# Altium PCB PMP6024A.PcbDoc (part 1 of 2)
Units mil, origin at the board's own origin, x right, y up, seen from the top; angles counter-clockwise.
Board outline 5700 x 1771.65 mil, 2 copper layers (Top Layer, Bottom Layer), stack 62 mil thick; 185 components, 92 nets, 398 pads, 91 vias.
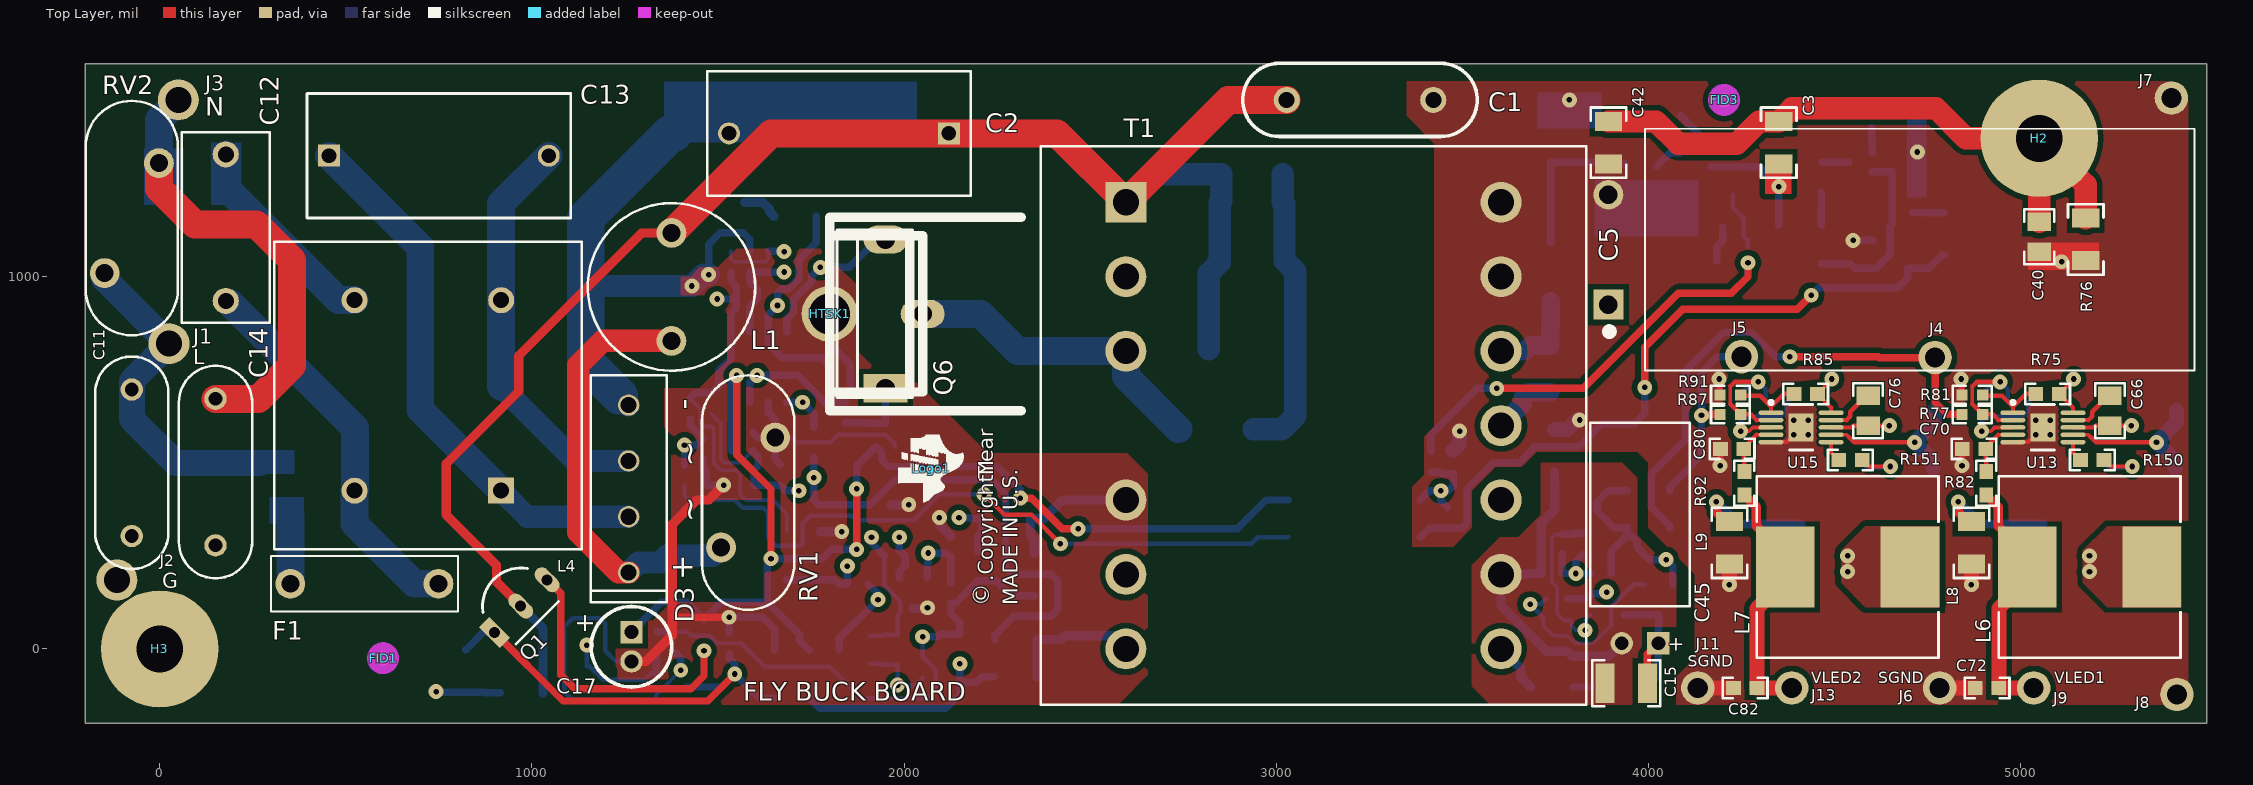
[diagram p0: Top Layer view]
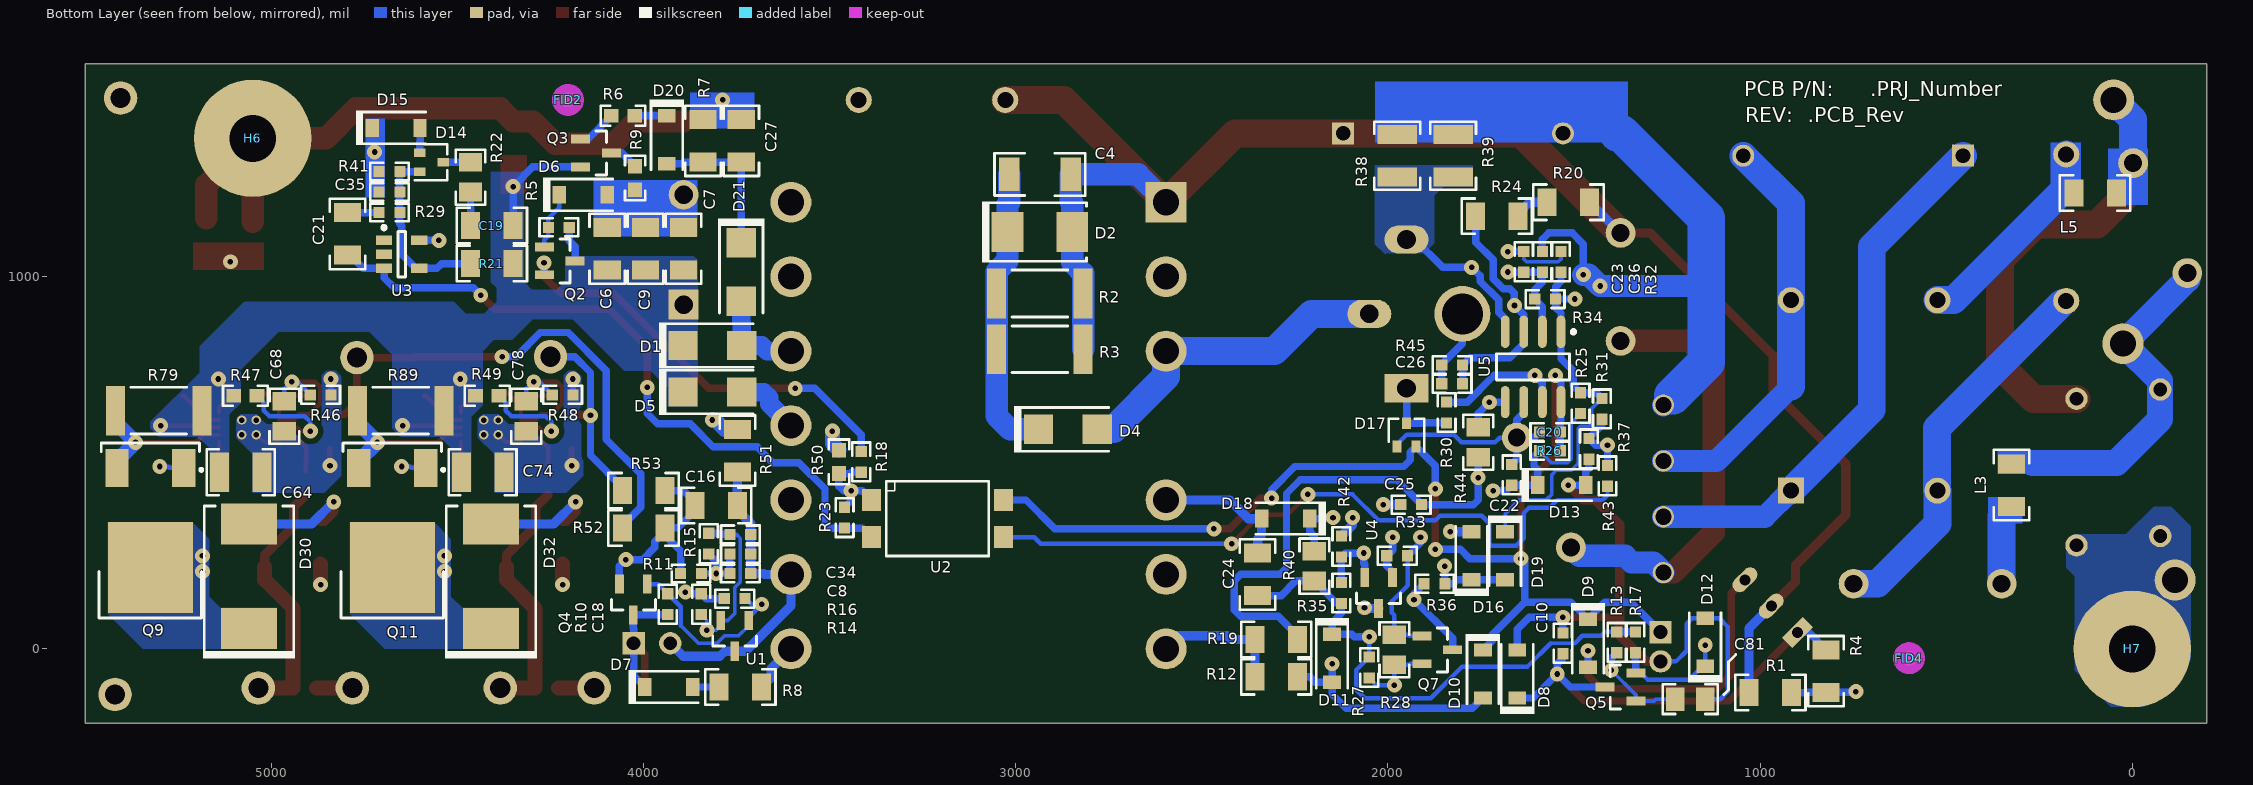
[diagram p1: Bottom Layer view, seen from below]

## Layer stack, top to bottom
Top Layer: signal copper 1.4
Dielectric: core 59.2, FR-4, Dk 4.8
Bottom Layer: signal copper 1.4

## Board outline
-200,-200 -200,1571.65 5500,1571.65 5500,-200

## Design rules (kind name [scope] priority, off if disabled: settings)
AcuteAngle [All] p1: minimum=4.50000000000000E+0001 checktracksonly=FALSE
AssemblyTestPointUsage [All] p1: valid=2
Clearance Clearance_U13&U15 [InComponent('U13')or InComponent('U15')] p1: gap=7
Clearance Poly_clearance [InPoly] p2: gap=15
Clearance [All] p3: gap=8
ComponentClearance TO-220+heatsink [InComponent('HTSK1') vs InComponent('Q6')] p1: gap=-1 collisioncheckmode=3 verticalgap=-1 showdistances=FALSE
ComponentClearance Hardware [(HasFootprint('NY PMS 440 0025 PH')) vs HasFootprint('Keystone_1902C')] p2: gap=-1 collisioncheckmode=3 verticalgap=-1 showdistances=FALSE
ComponentClearance ComponentClearance_SmallPassives [HasFootprint('0201*') or HasFootprint('0402*') or HasFootprint('0508') or HasFootprint('0603*') or HasFootprint('0612') or HasFootprint('0805*') or HasFootprint('0815*') or HasFootprint('0830*') or HasFootprint('1206*') or HasFootprint('1210*') or HasFootprint('1808*') or HasFootprint('1812*') or HasFootprint('1825*') or HasFootprint('2010*') or HasFootprint('2220*') or HasFootprint('2225*') or HasFootprint('2512*') or HasFootprint('2728*') or HasFootprint('3518*') vs HasFootprint('0201*') or HasFootprint('0402*') or HasFootprint('0508') or HasFootprint('0603*') or HasFootprint('0612') or HasFootprint('0805*') or HasFootprint('0815*') or HasFootprint('0830*') or HasFootprint('1206*') or HasFootprint('1210*') or HasFootprint('1808*') or HasFootprint('1812*') or HasFootprint('1825*') or HasFootprint('2010*') or HasFootprint('2220*') or HasFootprint('2225*') or HasFootprint('2512*') or HasFootprint('2728*') or HasFootprint('3518*')] p3: gap=10 collisioncheckmode=3 verticalgap=10 showdistances=FALSE
ComponentClearance [All] p4: gap=1 collisioncheckmode=3 verticalgap=1 showdistances=FALSE
DiffPairsRouting [All] p1: maxlimit=100 minlimit=10 mostfreqgap=10 maxuncoupledlength=1000
FabricationTestPointUsage TestPointUsage [All] p1: valid=2 allowmultiple=FALSE
FabricationTestpoint Testpoint [All] p1: side=3 testpointundercomponent=TRUE minsize=40 maxsize=100 preferedsize=60 minholesize=0 maxholesize=40 preferedholesize=32 testpointgrid=1 allowsidetop=TRUE allowsidebottom=TRUE usegrid=TRUE gridtolerance=0.01
FanoutControl Fanout_LCC [IsLCC] p1: bgadir=Out bgaviamode=Centered fanoutstyle=Auto fanoutdirection=Alternating viagrid=1 // Fanout_LCC (Default Rule)
FanoutControl Fanout_BGA [IsBGA] p2: bgadir=Out bgaviamode=Centered fanoutstyle=Auto fanoutdirection=Alternating viagrid=1 // Fanout_BGA (Default Rule)
FanoutControl Fanout_Default [All] p4: bgadir=Out bgaviamode=Centered fanoutstyle=Auto fanoutdirection=Alternating viagrid=1 // Fanout_Default (Default Rule)
FanoutControl Fanout_Small [(CompPinCount < 5)] p5: bgadir=Out bgaviamode=Centered fanoutstyle=Auto fanoutdirection=OutThenIn viagrid=1 // Fanout_Small (Default Rule)
Height [All] p1: minheight=0 maxheight=1500 prefheight=500
HoleSize [All] p1: absolutevalues=TRUE maxlimit=251 minlimit=8 maxpercent=80.000 minpercent=20.000
MinimumAnnularRing [All] p1: minimumring=4.9
MinimumSolderMaskSliver MinimumSolderMaskSliver_Logo [InComponentClass('Logo') vs InComponentClass('Logo')] p1: minsoldermaskwidth=0.7
MinimumSolderMaskSliver [All] p2: minsoldermaskwidth=4
PlaneConnect [All] p1: planeconnectstyle=Relief reliefexpansion=10 reliefentries=4 reliefconductorwidth=10 reliefairgap=10
PolygonConnect [All] p1: connectstyle=Direct reliefconductorwidth=10 reliefentries=4 polygonreliefangle="90 Angle" airgapwidth=10
RoutingVias [All] p1: holewidth=15 width=32 viastyle="Through Hole" minholewidth=15 minwidth=25 maxholewidth=15 maxwidth=40
SMDToCorner [All] p1 off: distance=30000
SilkToSilkClearance [All] p1: silktosilkclearance=5
SilkscreenOverComponentPads [All] p1: minsilkscreentomaskgap=5
SolderMaskExpansion [All] p1: expansion=3
UnRoutedNet [All] p1 off:
Width [All] p1: maxlimit=100 minlimit=6 preferedwidth=10 checkconnectedcopper=TRUE
12 further rules are at their usual default settings.

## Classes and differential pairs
component class AssemblyNote: ZZ2 ZZ3 ZZ4
component class FiducialMark: FID1 FID2 FID3 FID4
component class PMP6024A_Hardware: FID1 FID2 FID3 FID4 Logo1 ZZ2 ZZ3 ZZ4
component class Logo: Logo1
component class "Mounting Holes": H2 H3
component class PMP6024A_pg1: C1 C2 C3 C4 C5 C6 C7 C8 C9 C10 C11 C12 C13 C14 C15 C16 C17 C18 C19 C20 C21 C22 C23 C24 C25 C26 C27 C34 C35 C36 C42 C45 C81 D1 D2 D3 D4 D5 D6 D7 D8 D9 D10 D11 D12 D13 D14 D15 D16 D17 D18 D19 D20 D21 F1 H2 H3 H6 H7 HTSK1 J1 J2 J3 L1 L3 L4 L5 Q1 Q2 Q3 Q4 Q5 Q6 Q7 R1 R2 R3 R4 R5 R6 R7 R8 R9 R10 R11 R12 R13 R14 R15 R16 R17 R18 R19 R20 R21 R22 R23 R24 R25 R26 R27 R28 R29 R30 R31 R32 R33 R34 R35 R36 R37 R38 R39 R40 R41 R42 R43 R44 R45 R50 R51 R76 RV1 RV2 T1 U1 U2 U3 U4 U5
component class PMP6024A_pg2: C40 C64 C66 C68 C70 C72 C74 C76 C78 C80 C82 D30 D32 J4 J5 J6 J7 J8 J9 J11 J13 L6 L7 L8 L9 Q9 Q11 R46 R47 R48 R49 R52 R53 R75 R77 R79 R81 R82 R85 R87 R89 R91 R92 R150 R151 U13 U15

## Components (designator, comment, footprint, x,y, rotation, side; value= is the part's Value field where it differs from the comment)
C1 "VY1472M63Y5UQ63V0" Cap_NP_16Dx5W-10LS 3225,1475 r180 top
C2 "B32922C3334M" B32922_14.5mm 1825,1385 r180 top locked
C3 "GRM319R72A104KA01D" 1206 4350,1360 r90 top
C4 "VJ1808Y103KXGAT" 1808 2935,1275 r0 bottom
C5 "UPW1J102MHD6" CAP_POL-16.5Dx37.5T-7.5LS_Horz 3892.5,925 r90 top locked
C6 "GRM31CR72A105KA01L" 1206 4097.5,1075 r90 bottom
C7 "GRM31CR72A105KA01L" 1206 3892.5,1075 r90 bottom
C8 "C0603C222K5RACTU" 0603_HV 3740,255 r180 bottom
C9 "GRM31CR72A105KA01L" 1206 3995,1075 r90 bottom
C10 "DNP" 0603_HV 1530,15 r90 bottom
C11 "VY2682M59Y5US63V0" Cap_NP_14.5Lx5W-10LS -75,500 r270 top
C12 "B32921C3104M" Cap_NP_13Lx6W-10LS 177.5,935 r90 top
C13 "B32922C3334M" B32922_14.5mm 750,1325 r0 top locked
C14 "VY2682M59Y5US63V0" Cap_NP_14.5Lx5W-10LS 150,475 r90 top locked
C15 "GRM32RR71H105KA01L" 1210 3940,-92.5 r180 top
C16 "GRM31CR72A105KA01L" 1206 3805,385 r180 bottom
C17 "EEU-EB1E470S" Cap_Pol_5Dx11T-2LS 1267.5,45 r270 top
C18 "GRM1885C2A471JA01D" 0603_HV 3845,120 r270 bottom
C19 "GRM31MR72A474KA35L" 1206 4407.5,1137.5 r0 bottom
C20 "GRM188R71H104KA93D" 0603_HV 1565,582.5 r0 bottom
C21 "GRM31CR71A106KA01L" 1206 4795,1115 r90 bottom
C22 "GRM188R71E224KA88D" 0603_HV 1667.5,467.5 r90 bottom
C23 "GRM188R71H104KA93D" 0603_HV 1635,1040 r270 bottom
C24 "GRM31CR72A105KA01L" 1206 2350,200 r90 bottom
C25 "GRM1885C2A220JA01D" 0603_HV 1937.5,387.5 r180 bottom
C26 "GRM188R72A102KA01D" 0603_HV 1827.5,712.5 r0 bottom
C27 "GRM31CR72A105KA01L" 1206 3737.5,1365 r90 bottom
C34 "GRM1885C2A471JA01D" 0603_HV 3740,307.5 r180 bottom
C35 "C0603C222K5RACTU" 0603_HV 4682.5,1227.5 r0 bottom
C36 "C0603C222K5RACTU" 0603_HV 1585,1040 r90 bottom
C40 "C0805C104K1RACTU" 0805_HV 5050,1107.5 r90 top
C42 "GRM319R72A104KA01D" 1206 3892.5,1360 r270 top
C45 "UPW1H470MED" Cap_Pol_6.3Dx11T-2.5LS_horz 3977.5,15 r180 top locked
C64 "HMK325B7225KN-T" 1210 5082.5,475 r0 bottom
C66 "GRM21BR71H105KA12L" 0805_HV 5240,640 r270 top
C68 "GRM21BR61C106KE15L" 0805_HV 4965,625 r270 bottom
C70 "GRM188R71H471KA01D" 0603 4875,537.5 r180 top
C72 "GRM188R71H103KA01D" 0603 4910,-105 r180 top
C74 "HMK325B7225KN-T" 1210 4432.5,475 r0 bottom
C76 "GRM21BR71H105KA12L" 0805_HV 4590,640 r270 top
C78 "GRM21BR61C106KE15L" 0805_HV 4315,625 r270 bottom
C80 "GRM188R71H471KA01D" 0603 4225,537.5 r180 top
C81 "C2012X5R1C475K125AC" 0805_HV 1187.5,-135 r180 bottom
C82 "GRM188R71H103KA01D" 0603 4260,-105 r180 top
D1 "MURA140T3G" SMA 3815,815 r180 bottom
D2 "P6SMB220A" SMB 2935,1120 r180 bottom
D3 "2KBP08M-E4/51" KBPM 1260,430 r90 top locked
D4 "US1K-E3/61T" SMA 2860,590 r180 bottom
D5 "MURA140T3G" SMA 3815,690 r180 bottom
D6 "MMSZ5240B-7-F" SOD-123 4162.5,1220 r180 bottom
D7 "BAV19W-7-F" SOD-123 3932.5,-102.5 r180 bottom
D8 "MMSZ5248B-7-F" SOD-123 1652.5,-67.5 r90 bottom
D9 "BAV19W-7-F" SOD-123 1462.5,15 r270 bottom
D10 "BAV19W-7-F" SOD-123 1745,-67.5 r270 bottom
D11 "BAV19W-7-F" SOD-123 2150,-25 r270 bottom
D12 "MMSZ5240B-7-F" SOD-123 1147.5,17.5 r90 bottom
D13 "MMSZ5240B-7-F" SOD-123 1532.5,440 r180 bottom
D14 "BAV99WT1G" SOT-323 4570,1307.5 r180 bottom
D15 "MMSZ5230B-7-F" SOD-123 4665,1400 r180 bottom
D16 "MMSZ5225B-7-F" SOD-123 1775,250 r90 bottom
D17 "BAV99WT1G" SOT-323 1950,575 r90 bottom
D18 "MMSZ5245B-7-F" SOD-123 2275,350 r0 bottom
D19 "BAV19W-7-F" SOD-123 1685,250 r270 bottom
D20 "MMSZ5230B-7-F" SOD-123 3937.5,1367.5 r270 bottom
D21 "MURA140T3G" SMA 3737.5,1012.5 r270 bottom
D30 "CDBC560-G" SMC 5060,195 r90 bottom
D32 "CDBC560-G" SMC 4410,195 r90 bottom
F1 "0447003.YXP" Fuse_447series 550,175 r180 top
FID1 "Fiducial" Fiducial10-20 600,-25 r0 top
FID2 "Fiducial" Fiducial10-20 4203,1475 r180 bottom
FID3 "Fiducial" Fiducial10-20 4203,1475 r0 top
FID4 "Fiducial" Fiducial10-20 600,-25 r180 bottom
H2 "NY PMS 440 0025 PH" "NY PMS 440 0025 PH" 5050,1371.65 r0 top
H3 "NY PMS 440 0025 PH" "NY PMS 440 0025 PH" 0,0 r0 top
H6 "1902C" Keystone_1902C 5050,1371.65 r180 bottom locked
H7 "1902C" Keystone_1902C 0,0 r180 bottom locked
HTSK1 "7141DG" Htsk_7147DG 1800,900 r270 top locked
J1 "TESTPOINT" Hole_R110D70 25,820 r0 top
J2 "TESTPOINT" Hole_R110D70 -115,185 r0 top
J3 "TESTPOINT" Hole_R110D70 50,1475 r0 top
J4 "NA" "CONN-18GA WIRE" 4770,782.5 r0 top
J5 "NA" "CONN-18GA WIRE" 4250,785 r90 top
J6 "NA" "CONN-18GA WIRE" 4782.5,-105 r180 top
J7 "NA" "CONN-18GA WIRE" 5405,1480 r0 top
J8 "NA" "CONN-18GA WIRE" 5420,-122.5 r0 top
J9 "NA" "CONN-18GA WIRE" 5035,-105 r180 top
J11 "NA" "CONN-18GA WIRE" 4132.5,-105 r90 top
J13 "NA" "CONN-18GA WIRE" 4385,-105 r90 top
L1 "RFB1010-561L" Indt_RL5480-4 1375,827.5 r90 top locked
L3 "HI1206T161R-10" 1206 325,440 r270 bottom
L4 "EH20-0.8-02-5M6" Schaffner_EH20-0.8-02-5M6 917.5,425 r90 top locked
L5 "HI1206T161R-10" 1206 100,1225 r0 bottom
L6 "MSS1260-154KL" MSS1260 5185.3,220 r180 top
L7 "MSS1260-154KL" MSS1260 4535.3,220 r180 top
L8 "HI1206T161R-10" 1206 4867.5,285 r90 top
L9 "HI1206T161R-10" 1206 4217.5,285 r90 top
Logo1 "Texas Instruments" TI_Symbol_Overlay_Small 2072.5,485 r90 top
Q1 "FQN1N60CTA" TO92_modified 970,115 r315 top
Q2 "MMBT3904" MF03A_N 4225,1042.5 r180 bottom
Q3 "MMBTA56-7-F" MF03A_N 4127.5,1332.5 r180 bottom
Q4 "MMBT3904" MF03A_N 4027.5,132.5 r270 bottom
Q5 "MMBT3904" MF03A_N 1375,-102.5 r0 bottom
Q6 "STP10NK80ZFP" TO-220AB-wide 1950,900 r90 top locked
Q7 "MMBT3906-7-F" MF03A_N 1867.5,-2.5 r180 bottom
Q9 "ZXMP7A17KTC" DPAK 5325,352.5 r270 bottom
Q11 "ZXMP7A17KTC" DPAK 4675,352.5 r270 bottom
R1 "CRCW1206499KFKEA" 1206 972.5,-117.5 r180 bottom
R2 "CRCW251262K0JNEG" 2512 2935,955 r180 bottom
R3 "DNP" 2512 2935,805 r180 bottom
R4 "CRCW1206499KFKEA" 1206 822.5,-60 r90 bottom
R5 "CRCW060349K9FKEA" 0603_HV 4227.5,1132.5 r180 bottom
R6 "CRCW060320K0FKEA" 0603 4055,1432.5 r0 bottom
R7 "CRCW1206200KFKEA" 1206 3840,1365 r270 bottom
R8 "CRCW120620R0JNEA" 1206 3740,-102.5 r0 bottom
R9 "CRCW06031K00FKEA" 0603 4022.5,1265 r90 bottom
R10 "CRCW06032K21FKEA" 0603_HV 3935,120 r270 bottom
R11 "CRCW0603249KFKEA" 0603_HV 3872.5,202.5 r0 bottom
R12 "CRCW120620R0JNEA" 1206 2300,-75 r180 bottom
R13 "CRCW0603100KFKEA" 0603_HV 1385,17.5 r90 bottom
R14 "CRCW06031M00FKEA" 0603_HV 3755,135 r180 bottom
R15 "CRCW060310K0FKEA" 0603_HV 3825,282.5 r270 bottom
R16 "CRCW060349K9FKEA" 0603_HV 3740,202.5 r0 bottom
R17 "CRCW06031K00JNEA" 0603_HV 1335,17.5 r90 bottom
R18 "CRCW06031K00JNEA" 0603_HV 3415,502.5 r90 bottom
R19 "CRCW120622K1FKEA" 1206 2300,25 r0 bottom
R20 "CRCW12061M00FKEA" 1206 1515,1200 r180 bottom
R21 "CRCW1206499KFKEA" 1206 4407.5,1035 r0 bottom
R22 "CRCW0805150RFKEA" 0805_HV 4465,1267.5 r270 bottom
R23 "CRCW0603100KFKEA" 0603_HV 3460,352.5 r90 bottom
R24 "CRCW12061M00FKEA" 1206 1707.5,1162.5 r180 bottom
R25 "CRCW0603681KFKEA" 0603_HV 1482.5,660 r90 bottom
R26 "CRCW060349K9FKEA" 0603_HV 1565,532.5 r180 bottom
R27 "CRCW060310R0FKEA" 0603_HV 2050,-50 r270 bottom
R28 "CRCW0805150RFKEA" 0805_HV 1982.5,-2.5 r270 bottom
R29 "CRCW060320K0FKEA" 0603_HV 4682.5,1172.5 r0 bottom
R30 "CRCW060320R0FKEA" 0603_HV 1842.5,635 r270 bottom
R31 "CRCW060347K5FKEA" 0603_HV 1425,645 r90 bottom
R32 "CRCW060347K5FKEA" 0603_HV 1535,1040 r270 bottom
R33 "CRCW06032K21FKEA" 0603_HV 1975,250 r180 bottom
R34 "CRCW060375K0FKEA" 0603_HV 1577.5,940 r180 bottom
R35 "CRCW060375K0FKEA" 0603_HV 2125,150 r270 bottom
R36 "CRCW06031K00JNEA" 0603_HV 1875,175 r180 bottom
R37 "CRCW06032K21FKEA" 0603_HV 1460,537.5 r90 bottom
R38 "MCR25JZHFLR470" 1210 1975,1325 r270 bottom
R39 "MCR25JZHFLR470" 1210 1825,1325 r270 bottom
R40 "CRCW0805150RFKEA" 0805_HV 2197.5,222.5 r270 bottom
R41 "CRCW060312K7FKEA" 0603_HV 4682.5,1282.5 r180 bottom
R42 "CRCW060314K3FKEA" 0603_HV 2125,275 r270 bottom
R43 "CRCW06034K99FKEA" 0603_HV 1410,465 r270 bottom
R44 "CRCW0805150RFKEA" 0805_HV 1757.5,555 r90 bottom
R45 "CRCW060312K1FKEA" 0603_HV 1827.5,762.5 r180 bottom
R46 "CRCW06032K87FKEA" 0603_HV 4867.5,682.5 r180 bottom
R47 "CRCW0603100KFKEA" 0603 5070,680 r180 bottom
R48 "CRCW06032K87FKEA" 0603_HV 4217.5,682.5 r180 bottom
R49 "CRCW0603100KFKEA" 0603 4420,680 r180 bottom
R50 "CRCW0603100KFKEA" 0603 3475,502.5 r270 bottom
R51 "CRCW12060000Z0EA" 1206 3747.5,532.5 r90 bottom
R52 "CRCW1206280KFKEA" 1206 4000,325 r0 bottom
R53 "CRCW1206280KFKEA" 1206 4000,425 r0 bottom
R75 "CRCW0603249KFKEA" 0603 5072.5,685 r180 top
R76 "CRCW12061M00FKEA" 1206 5175,1100 r270 top
R77 "CRCW060310K0FKEA" 0603_HV 4870,630 r180 top
R79 "ERJ-1TRSJR18U" 2512 5302.5,640 r180 bottom
R81 "CRCW06036K98FKEA" 0603_HV 4870,682.5 r0 top
R82 "CRCW060364K9FKEA" 0603 4907.5,445 r90 top
R85 "CRCW0603200KFKEA" 0603 4422.5,685 r180 top
R87 "CRCW060310K0FKEA" 0603_HV 4220,630 r180 top
R89 "ERJ-1TRSJR18U" 2512 4652.5,640 r180 bottom
R91 "CRCW06036K98FKEA" 0603_HV 4220,682.5 r0 top
R92 "CRCW060364K9FKEA" 0603 4257.5,445 r90 top
R150 "CRCW06036R80JNEA" 0603 5192.5,507.5 r0 top
R151 "CRCW06036R80JNEA" 0603 4542.5,507.5 r0 top
RV1 "S14K320E2K1" MOV_S14K320E2K1 1581,420 r270 top locked
RV2 "S14K320E2K1" MOV_S14K320E2K1 -75,1157.5 r270 top
T1 "" Xfmr_ETD29H_Wurth 3100,600 r0 top locked
U1 "LM431BIM3" MF03A_N 3755,35 r270 bottom
U2 "FOD817ASD" FOD81XASD 3210,350 r180 bottom
U3 "LMV431AIM5X" MF05A_N 4650,1060 r180 bottom
U4 "LM431BIM3" MF03A_N 2025,150 r270 bottom
U5 "UCC28811DR" D0008A_N 1610,757.5 r270 bottom
U13 "LM3409HVMY/NOPB" MUC10A_N 5060,595 r0 top
U15 "LM3409HVMY/NOPB" MUC10A_N 4410,595 r0 top
ZZ2 "These assemblies are ESD sensitive, ESD precautions shall be observed." AssemblyNote 2.5,2031.61 r0 top
ZZ3 "These assemblies must be clean and free from flux and all contaminants. Use of no clean flux is not acceptable." AssemblyNote 2.5,1943.06 r0 top
ZZ4 "These assemblies must comply with workmanship standards IPC-A-610 Class 2., unless otherwise specified." AssemblyNote 2.5,1854.5 r0 top

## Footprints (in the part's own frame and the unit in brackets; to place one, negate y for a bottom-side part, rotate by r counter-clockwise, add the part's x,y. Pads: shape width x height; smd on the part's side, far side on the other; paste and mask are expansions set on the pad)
0603 [mm] "0603 from SM-752 data"
  rect 1x0.95 smd: 1(-0.8,0) 2(0.8,0)
  silkscreen extent -1.52,-0.69 1.52,0.69, body extent -0.87,-0.47 0.87,0.47, height 0.85
0603_HV [mil] "Ernesto recommended land pattern.  26 mil between pads."
  rect 30x30 smd: 1(-28,0) 2(28,0)
  silkscreen extent -52,-24 52,24, body extent -34,-19 34,19, height 33
0805_HV [mil] "0805 with 30mil clearance between pads"
  rect 50x63 smd: 1(-40,0) 2(40,0)
  silkscreen extent -74,-40 74,40, body extent -43,-29 43,29, height 43
1206 [mm] "1206 from SM-752 data"
  rect 1.3x1.85 smd: 1(-1.45,0) 2(1.45,0)
  silkscreen extent -2.4,-1.21 2.4,1.21, body extent -1.7,-0.9 1.7,0.9, height 1.35
1210 [mm] "1210 from SM-752 data"
  rect 1.3x2.7 smd: 1(-1.45,0) 2(1.45,0)
  silkscreen extent -2.32,-1.57 2.32,1.57, body extent -1.7,-1.35 1.7,1.35, height 1.35
1808 [mm] "Chip Capacitor, Body 4.6x2.0mm, IPC Medium Density"
  rect 1.4x2.3 smd: 1(-2.1,0) 2(2.1,0)
  silkscreen extent -3.1,-1.45 3.1,1.45, body extent -2.47,-1.2 2.47,1.2, height 2.03
2512 [mm] "Chip Resistor, Body 6.3x3.2mm, IPC Medium Density"
  rect 1.3x3.4 smd: 1(-2.95,0) 2(2.95,0)
  silkscreen extent -1.9,-1.6 1.9,1.6, body extent -3.22,-1.67 3.22,1.67, height 0.71
AssemblyNote [mil] "Assembly Note"
B32922_14.5mm [mm] "Epcos film capacitors, 15mm spacing"
  rect 1.5x1.5 hole 1: 1(-7.5,0)
  round 1.5 hole 1: 2(7.5,0)
  silkscreen extent -9,-4.25 9,4.25, body extent -9,-4.25 9,4.25, height 14.5
Cap_NP_13Lx6W-10LS [mil] "Epcos P/N B32921C3104M"
  round 70 hole 43: 1(0,0) 2(393.7,0)
  silkscreen extent -59,-118 453,118, body extent -59,-118 453,118, height 472
Cap_NP_14.5Lx5W-10LS [mil]
  round 60 hole 37: 1(-196.85,0) 2(196.85,0)
  silkscreen extent -285,-98 285,98, body extent -284,-100 284,97, height 688
Cap_NP_16Dx5W-10LS [mil]
  round 70 hole 43: 1(-196.85,0) 2(196.85,0)
  silkscreen extent -315,-98 315,98, body extent -312,-97 315,99, height 787
CAP_POL-16.5Dx37.5T-7.5LS_Horz [mil] "Nichicon P/N UPW1J102MHD6"
  rect 80x80 hole 50: 1(0,0)
  round 80 hole 50: 2(295.28,0)
  silkscreen extent -177,-1575 472,7, body extent -177,-1575 471,-99, height 915
Cap_Pol_5Dx11T-2LS [mil]
  rect 60x60 hole 37: 1(0,0)
  round 60 hole 37: 2(78.74,0)
  silkscreen extent -69,-108 148,108, body extent -68,-108 148,108, height 472
Cap_Pol_6.3Dx11T-2.5LS_horz [mil]
  rect 60x60 hole 37: 1(-49.21,0)
  round 60 hole 37: 2(49.21,0)
  silkscreen extent -134,-592 134,-100, body extent -133,-592 133,-100, height 299
"CONN-18GA WIRE" [mil]
  round 90 hole 54: 1(0,0)
D0008A_N [mm] "SOIC, 8-Leads, Body 4.9x3.9mm, Pitch 1.27mm, IPC Medium Density"
  oval 2.2x0.6 smd: 1(-2.4,1.905) 2(-2.4,0.635) 3(-2.4,-0.635) 4(-2.4,-1.905) 5(2.4,-1.905) 6(2.4,-0.635) 7(2.4,0.635) 8(2.4,1.905)
  silkscreen extent -2.52,-2.5 0.9,2.88, body extent -2,-2.5 2,2.5, height 1.75
DPAK [mm] "D-PAK, 3-Pads, Body 6.22x6.73mm (max), TO-252AA using nominal STEP model"
  rect 2.6x1.6 smd: 1(-3.4,2.28) 3(-3.4,-2.28)
  rect 6.2x5.8 smd paste-2.9: 4(3.4,0)
  silkscreen extent -5.1,-3.5 6.83,3.55, body extent -3.86,-3.29 5.84,3.29, height 2.48
Fiducial10-20 [mm]
  round 1 smd paste-0.5 mask+0.5: 1(0,0)
  Keep-Out Layer circle w1.178: c0,0 r0.5
FOD81XASD [mm] "Fairchild FOD814-817ASD series high temp optocouplers"
  rect 1.3x1.5 smd mask+0.076: 1(-4.5,1.27) 2(-4.5,-1.27) 3(4.5,-1.27) 4(4.5,1.27)
  silkscreen extent -3.5,-2.55 3.5,2.55, body extent -3.5,-2.55 3.5,2.55, height 4
Fuse_447series [mil] "Littelfuse 447 series"
  round 80 hole 48: 1(-199.02,0) 2(199.02,0)
  silkscreen extent -251,-75 251,75, body extent -251,-75 251,75, height 345
Hole_R110D70 [mil]
  round 110 hole 70: 1(0,0)
Htsk_7147DG [mil] "Aavid P/N 7147DG TO-220 heatsink"
  round 150 hole 110: 1(0,0)
  silkscreen extent -260,0 260,515, body extent -273,-13 272,515, height 900
Indt_RL5480-4 [mil] "Renco Electronics inductor RL-5480-4"
  round 80 hole 48 mask+2: 1(0,0) 2(290,0)
  silkscreen extent -80,-225 370,225, body extent -80,-225 368,224, height 710
KBPM [mm] "Vishay Bridge Rectifier"
  round 1.45 hole 1.1: 1(-5.715,0) 2(-1.905,0) 3(1.905,0) 4(5.715,0)
  silkscreen extent -7.75,-2.6 7.75,2.6, body extent -7.62,-2.68 7.62,2.4, height 12.7
Keystone_1902C [mil] "Hex Standoff, 4-40 threaded, nylon"
  body extent -145,-126 146,126, height 501
MF03A_N [mm] "SOT23, 3-Leads, Body 2.9x1.3mm, Pitch 0.95mm, Lead Span 2.4mm, IPC Medium Density"
  rect 1.3x0.6 smd: 1(-1.05,0.95) 2(-1.05,-0.95) 3(1.05,0)
  silkscreen extent 0,-1.5 0.7,1.5, body extent -0.7,-1.5 0.7,1.5, height 1.12
MF05A_N [mm] "SOT23, 5-Leads, Body 2.9x1.6mm, Pitch 0.95mm, Lead Span 2.8mm, IPC Medium Density"
  rect 1.1x0.65 smd: 1(-1.2,0.95) 2(-1.2,0) 3(-1.2,-0.95) 4(1.2,-0.95) 5(1.2,0.95)
  silkscreen extent -1.33,-1.55 0.25,1.95, body extent -0.9,-1.55 0.9,1.55, height 1.19
MOV_S14K320E2K1 [mil] "Epcos P/N S14K320E2K1"
  round 80 hole 48: 1(-147.64,72.83) 2(147.64,-72.83)
  silkscreen extent -315,-124 315,124, body extent -314,-124 314,124, height 747
MSS1260 [mm]
  rect 4x5.5 smd: 1(-4.25,0) 2(4.25,0)
  silkscreen extent -6.2,-6.2 6.2,6.2, body extent -6.15,-6.15 6.15,6.15, height 6.25
MUC10A_N [mm] "TSSOP, 10-Leads, Body 3x3mm, Pitch 0.5mm, Exposed Pad, IPC Medium Density"
  oval 1.7x0.3 smd: 1(-2.05,1) 2(-2.05,0.5) 3(-2.05,0) 4(-2.05,-0.5) 5(-2.05,-1) 6(2.05,-1) 7(2.05,-0.5) 8(2.05,0) 9(2.05,0.5) 10(2.05,1)
  rect 1.73x1.9 smd: 11(0,0)
  silkscreen extent -2.17,-1.55 0.8,1.82, body extent -1.55,-1.55 1.55,1.55, height 1.1
"NY PMS 440 0025 PH" [mm] "4-40 nylon screw and mounting hole"
  round 8 hole 3.2: 1(0,0)
  body extent -3.3,-3.3 3.3,3.3, height 2.69
Schaffner_EH20-0.8-02-5M6 [mil]
  rect 70x70 hole 43: 1(0,0)
  round 70 hole 43: 2(0,393.7) 3(511.81,393.7) 4(511.81,0)
  silkscreen extent -157,-217 669,610, body extent -162,-222 674,615, height 701
SMA [mm] "Molded Diode, 2-Leads, Body 4.3x2.6mm, IPC Medium Density, based on OnSemi component dimensions and land pattern"
  rect 2x2 smd: 1(-2,0) 2(2,0)
  silkscreen extent -3.66,-1.57 2.79,1.57, body extent -2.6,-1.3 2.6,1.3, height 2.42
SMB [mil] "Molded Diode, 2-Leads, Body 5.4x3.6mm, IPC Medium Density, based on OnSemi component dimensions"
  rect 85x107.99 smd: 1(-87.01,0) 2(87.01,0)
  silkscreen extent -155,-82 125,82, body extent -106,-71 106,71, height 91
SMC [mil] "Molded Diode, 2-Leads, Body 6.9x5.8mm, IPC Medium Density, based on OnSemi component dimensions and land patterns"
  rect 110x150 smd: 1(-140.49,0) 2(140.49,0)
  silkscreen extent -221,-123 189,124, body extent -156,-116 156,116, height 91
SOD-123 [mm] "On Semi recommended land pattern"
  rect 0.915x1.22 smd: 1(-1.637,0) 2(1.637,0)
  silkscreen extent -2.74,-1.17 2.03,1.17, body extent -1.93,-0.9 1.93,0.9, height 1.35
SOT-323 [mm] "Zetex recommended land pattern.  March 2007"
  rect 0.8x0.6 smd: 1(-0.8,0.65) 2(-0.8,-0.65) 3(0.8,0)
  silkscreen extent -1.14,-1.22 1.09,1.22, body extent -1.13,-1.13 1.12,1.12, height 1.13
TI_Symbol_Overlay_Small [mil]
  silkscreen extent -90,-88 91,88
TO92_modified [mm] "TO, Flat Index; 3 In-Line, Axial Leads; Body Dia. 5mm; Leads 0.55 x 0.50 mm (max)"
  rect 2x1 hole 0.75: 1(0,-2.54)
  oval 2x1 hole 0.75: 2(0,0) 3(0,2.54)
  silkscreen extent -2.6,-2.13 1.6,2.13, body extent -2.61,-2.61 1.6,2.61, height 5.2
TO-220AB-wide [mil] "Copied from Altium's version of TO3B"
  rect 76x118.11 hole 50: 1(-200,0)
  oval 76x118.11 hole 50: 2(0,-100) 3(200,0)
  silkscreen extent -225,-73 225,130, body extent -221,-59 221,126, height 765
Xfmr_ETD29H_Wurth [mil] "P/N 750313746"
  rect 110x110 hole 70: 1(-503.94,600)
  round 110 hole 70: 2(-503.94,400) 3(-503.94,200) 5(-503.94,-200) 6(-503.94,-400) 7(-503.94,-600) 8(503.94,-600) 9(503.94,-400) 10(503.94,-200) 11(503.94,0) 12(503.94,200) 13(503.94,400) 14(503.94,600)
  round 0 all layers, no hole mask+0: 4(-503.94,0)
  silkscreen extent -732,-750 732,750, body extent -732,-750 732,750, height 1000

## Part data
C1: library part Capacitor, "CAP, CERM, 4700pF, 500VAC, Y5U, 20%, Radial 10mm"
C2 C13: "CAP, Film, 0.33uF, 630V, +/-20%, TH"
C3 C42: "CAP, CERM, 0.1uF, 100V, +/-10%, X7R, 1206"
C4: library part Capacitor, "CAP, CERM, 0.01uF, 1000V, X7R, 10%, 1808"
C5: library part Capacitor_Polarized, "CAP, Aluminum, 1000uF, 63V, +/-20%, Radial"
C6 C7 C9 C16 C24 C27: "CAP, CERM, 1uF, 100V, +/-10%, X7R, 1206"
C8 C35 C36: "CAP, CERM, 2200pF, 50V, +/-10%, X7R, 0603"
C10: library part GRM188R71E473KA01D
C11 C14: library part Capacitor, "CAP, Safety, 6800pF, 300VAC, Y5U, 20%, Radial, Disc"
C12: library part Capacitor, "CAP, FILM, 0.1uF, 305VAC, Radial"
C15: "CAP, CERM, 1uF, 50V, +/-10%, X7R, 1210"
C17: library part Capacitor_Polarized, "CAP, Aluminum, 47uF, 25V, +/-20%, Radial"
C18 C34: "CAP, CERM, 470pF, 100V, +/-5%, C0G/NP0, 0603"
C19: "CAP, CERM, 0.47uF, 100V, +/-10%, X7R, 1206"
C20 C23: "CAP, CERM, 0.1uF, 50V, +/-10%, X7R, 0603"
C21: "CAP, CERM, 10uF, 10V, +/-10%, X5R, 1206"
C22: "CAP, CERM, 0.22uF, 25V, +/-10%, X7R, 0603"
C25: "CAP, CERM, 22pF, 100V, +/-5%, C0G/NP0, 0603"
C26: "CAP, CERM, 1000pF, 100V, +/-10%, X7R, 0603"
C40: "CAP, CERM, 0.1uF, 100V, +/-10%, X7R, 0805"
C45: library part Capacitor_Polarized, "CAP, Alum, 47uF, 50V, +/-20%, Radial"
C64 C74: "CAP, CERM, 2.2uF, 100V, +/-10%, X7R, 1210"
C66 C76: "CAP, CERM, 1uF, 50V, +/-10%, X7R, 0805"
C68 C78: "CAP, CERM, 10uF, 16V, +/-10%, X5R, 0805"
C70 C80: "CAP, CERM, 470pF, 50V, +/-10%, X7R, 0603"
C72 C82: "CAP, CERM, 0.01uF, 50V, +/-10%, X7R, 0603"
C81: library part EMK212BJ475KG-T, "CAP, CERM, 4.7uF, 16V, +/-10%, X5R, 0805"
D1 D5 D21: library part Diode, "Diode, Ultrafas, 400V, 2A, SMA"
D2: library part TVS_Diode_Uni, "Diode, TVS, Uni, 600W, 220V, Unidirection, 5%, SMB"
D3: library part Diode_Bridge_Pos1_Neg4_AC23, "Diode, Switching-Bridge, 800V, 2A, SIP"
D4: library part Diode, "Diode, Ultrafast, 800V, 1A, SMA"
D6 D12 D13: "Diode, Zener, 10V, 500mW, SOD-123"
D7 D9 D10 D11 D19: library part Diode, "Diode, Fast, 100V, 200mA, SOD-123"
D8: "Diode, Zener, 18V, 500mW, SOD-123"
D14 D17: "Diode, P-N, 70V, 0.2A, SOT-323"
D15 D20: "Diode, Zener, 4.7V, 500mW, SOD-123"
D16: "Diode, Zener, 3V, 500mW, SOD-123"
D18: "Diode, Zener, 15V, 500mW, SOD-123"
D30 D32: library part Diode, "DIODE SCHOTTKY 60V 5A DO214AB"
F1: library part Fuse, "Fuse, 3A, 350VAC, Board Mount"
FID1 FID2 FID3 FID4: "Fiducial mark.  There is nothing to buy or mount."
H2 H3: library part "Chassis Screw", "Machine Screw, Round, #4-40 x 1/4, Nylon, Philips panhead"
H6 H7: "Standoff, Hex, 0.5\"L #4-40 Nylon"
HTSK1: library part Htsk_7141DG, "HTSK, Aavid P/N 7141DG, TO-220 Vert, PCB mount"
J1 J2 J3: "TEST POINT.  No entry in BOM."
J4 J5 J6 J7 J8 J9 J11 J13: library part "CONN_18GA HOLE", "18 GA WIRE HOLE"
L1: library part Inductor, "Inductor, 560uH, 1.05A, Radial"
L3 L5: library part Inductor, "Inductor, Ferrite EMI Chip, 160 Ohm @ 100KHz, 6A, 18m ohm, SMT"
L4: library part INDUCTOR_COUPLED, "Coupled Inductor, 5.6mH, 0.8A, 245m ohm, +/-15%, Through Hole"
L6 L7: library part Inductor, "Technology, Imax, DCR"
L8 L9: "6A Ferrite Bead, 160 ohm @ 100MHz, SMD"
Logo1: library part TI_Logo, "Texas Instrument Corporate Signature"
Q1: library part MOSFET_N, "MOSFET, N-CH, 600V, 300mA, TO-92"
Q2 Q4 Q5: library part "MMBT3904, Fairchild Semiconductor", "Transistor, NPN, 40V, 0.2A, SOT-23"
Q3: library part PNP, "Transistor, PNP, 80V, SOT23"
Q6: library part MOSFET_N, "MOSFET, N-CH, 800V, 9A, TO-220FP"
Q7: library part "MMBT3906-7-F, Diodes Inc.", "Transistor, PNP, 40V, 0.2A, SOT-23"
Q9 Q11: library part MOSFET_P, "MOSFET P-CH 70V 5.7A D PAK"
R1 R4 R21: "RES, 499k ohm, 1%, 0.25W, 1206"
R2: library part Resistor, "RES, 62k ohm, 5%, 1W, 2512"
R3: library part Resistor
R5 R16 R26: "RES, 49.9k ohm, 1%, 0.1W, 0603"
R6 R29: "RES, 20.0k ohm, 1%, 0.1W, 0603"
R7: "RES, 200k ohm, 1%, 0.25W, 1206"
R8 R12: "RES, 20 ohm, 5%, 0.25W, 1206"
R9: "RES, 1.00k ohm, 1%, 0.1W, 0603"
R10 R33 R37: "RES, 2.21k ohm, 1%, 0.1W, 0603"
R11 R75: "RES, 249k ohm, 1%, 0.1W, 0603"
R13 R23 R47 R49 R50: "RES, 100k ohm, 1%, 0.1W, 0603"
R14: "RES, 1.00Meg ohm, 1%, 0.1W, 0603"
R15 R77 R87: "RES, 10.0k ohm, 1%, 0.1W, 0603"
R17 R18 R36: "RES, 1.0k ohm, 5%, 0.1W, 0603"
R19: "RES, 22.1k ohm, 1%, 0.25W, 1206"
R20 R24 R76: "RES, 1.00Meg ohm, 1%, 0.25W, 1206"
R22 R28 R40 R44: "RES, 150 ohm, 1%, 0.125W, 0805"
R25: "RES, 681k ohm, 1%, 0.1W, 0603"
R27: "RES, 10.0 ohm, 1%, 0.1W, 0603"
R30: "RES, 20.0 ohm, 1%, 0.1W, 0603"
R31 R32: "RES, 47.5k ohm, 1%, 0.1W, 0603"
R34 R35: "RES, 75.0k ohm, 1%, 0.1W, 0603"
R38 R39: "RES, 0.47 ohm, 1%, 0.5W, 1210"
R41: "RES, 12.7k ohm, 1%, 0.1W, 0603"
R42: "RES, 14.3 k, 1%, 0.1 W, 0603"
R43: "RES, 4.99k ohm, 1%, 0.1W, 0603"
R45: "RES, 12.1k ohm, 1%, 0.1W, 0603"
R46 R48: "RES, 2.87 k, 1%, 0.1 W, 0603"
R51: "RES, 0 ohm, 5%, 0.25W, 1206"
R52 R53: "RES, 280k ohm, 1%, 0.25W, 1206"
R79 R89: library part Resistor, "RES .18 OHM 1W 5% 2512 SMD"
R81 R91: "RES, 6.98k ohm, 1%, 0.1W, 0603"
R82 R92: "RES, 64.9k ohm, 1%, 0.1W, 0603"
R85: "RES, 200k ohm, 1%, 0.1W, 0603"
R150 R151: "RES, 6.8 ohm, 5%, 0.1W, 0603"
RV1: library part Varistor_MetalOxide, "Varistor, 320VAC, 420VDC, 84J, 14mm, Disc"
RV2: library part Varistor_MetalOxide, "Varistor, 320VAC, 420VDC, 150J, 14mm, Disc"
T1: library part TFR_ETD29, "Xfmr, ETD Core, 450uH, 64 Np, 26 Ns, 8 Na1, 10 Na2, ETD29/16/10"
U1 U4: "Adjustable Precision Zener Shunt Regulator, 3-pin SOT-23"
U2: library part Opto-Isolator, "Optoisolator, Phototrans Out, 4-SMD"
U3: "Low-Voltage (1.24V) Adjustable Precision Shunt Regulators, 5-pin SOT-23"
U5: "LED Lighting Power Controller, -40 to +105 degC, 8-pin SOIC (D), Green (RoHS & no Sb/Br)"
U13 U15: "PFET Buck Controller for High Power LED Drives, 10-pin eMSOP, Pb-Free"
ZZ2 ZZ3 ZZ4: library part AssemblyNote

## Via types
v1: diameter 40, hole 15, Top Layer to Bottom Layer, 82 vias
v2: diameter 25, hole 15, Top Layer to Bottom Layer, 8 vias
v3: diameter 40, hole 15, Top Layer to Bottom Layer, tented bottom, 1 vias

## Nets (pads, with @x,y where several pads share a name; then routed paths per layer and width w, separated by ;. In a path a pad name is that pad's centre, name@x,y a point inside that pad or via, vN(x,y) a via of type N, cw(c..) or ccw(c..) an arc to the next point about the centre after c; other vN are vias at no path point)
+50V: C3.1 C5.1 C6.1 C7.1 C9.1 C19.1 C64.2 C66.2 C74.2 C76.2 D1.1 D5.1 Q2.3 Q3.2 R5.2 R21.1 R47.1 R49.1 R75.1 R79.2 R85.1 R89.2 U13.8 U13.10 U15.8 U15.10 | length 966
  Top Layer w10: U15.8@4490.71,595 4545,595 ; U15.10@4490.71,634.37 4490.71,648.29 ; U13.8@5140.71,595 5195,595 ; U13.10@5140.71,634.37 5140.71,648.29
  Top Layer w12: 4490.71,648.29 R85.1@4454,685 4492.5,723.5 v1(4492.5,725) ; 4545,595 4550,600 C76.2@4590,600 v1(4647.5,600) ; 5140.71,648.29 R75.1@5104,685 5142.5,723.5 v1(5142.5,725) ; 5195,595 5200,600 C66.2@5240,600 v1(5297.5,600)
  Bottom Layer w20: Q3.2@4168.84,1295.1 4297.4,1295.1 v1(4350.41,1242.09) C19.1@4350.41,1137.5 ; Q2.3@4183.66,1042.5 4183.66,1081.16 4199.5,1097 R5.2@4199.5,1132.5
DGND: C8.2 C15.2 C16.2 C34.2 C45.2 R16.1 R51.1 T1.9 U1.3 | length 876.2
  Bottom Layer w25: R51.1@3747.5,475.41 3747.5,435 3747.91,434.59 C16.2@3747.91,385 3747.91,372.91 3712,337 C34.2@3712,307.5 C8.2@3712,255 R16.1@3712,202.5 3677.5,202.5 3675,200 T1.9@3603.94,200 3603.94,116.06 3726.34,-6.34 U1.3@3755,-6.34 3781.34,-6.34 3795,-20 3893.29,-20 C45.2@3928.29,15
EGND: C3.2 C11.2 C14.1 C40.2 C42.1 H2.1 H3.1 J2.1 R76.1 | length 1745.5
  Top Layer w60: C42.1@3892.5,1417.09 4020.41,1417.09 4080,1357.5 4237.5,1357.5 4297.09,1417.09 C3.2@4350,1417.09 4385.41,1452.5 4772.5,1452.5 4853.35,1371.65 H2.1@5050,1371.65 ; C40.2@5050,1147.5 H2.1@5050,1371.65 ; R76.1@5175,1157.09 5175,1246.65 H2.1@5050,1371.65
ISO_15V: C16.1 Q4.2 R11.2 R52.1 R53.1 | length 574.9
  Bottom Layer w20: R11.2@3900.5,202.5 3900.5,263 3942.91,305.41 R52.1@3942.91,314.59 ; R53.1@3942.91,425 3892.5,425 3862.09,394.59 C16.1@3862.09,385 3862.09,370.41 3907.5,325 R52.1@3942.91,325 R52.1@3942.91,314.59 ; Q4.2@4064.9,173.84 4064.9,222.6 v1(4047.5,240) 4002.5,240 3970,272.5 3970,287.5 R52.1@3942.91,314.59
NetC1_2: C1.2 C2.1 C4.1 D2.2 L1.2 Q1.2 R1.1 R2.2 R3.2 R20.2 T1.1 | length 4482.9
  Top Layer w25: Q1.2@970,115 905,180 905,225 770,360 770,497.5 965,692.5 965,787.5 1295,1117.5 L1.2@1375,1117.5
  Top Layer w75: L1.2@1375,1117.5 1642.5,1385 2411.06,1385 T1.1@2596.06,1200 2871.06,1475 C1.2@3028.15,1475
  Bottom Layer w25: Q1.2@970,115 1029.59,55.41 R1.1@1029.59,-117.5 ; L1.2@1375,1117.5 1375.41,1117.5 R20.2@1457.91,1200
  Bottom Layer w60: T1.1@2596.06,1200 2671.06,1275 C4.1@2852.32,1275 2852.5,1274.82 2852.5,1202.5 2847.99,1197.99 D2.2@2847.99,1120 2847.99,1037.99 2818.86,1008.86 R2.2@2818.86,955 R3.2@2818.86,805
NetC4_2: C4.2 D2.1 D4.1 R2.1 R3.1 | length 790.1
  Bottom Layer w60: D4.1@2938.74,590 3015,590 3051.14,626.14 R3.1@3051.14,805 R2.1@3051.14,955 3051.14,1013.86 3022.01,1042.99 D2.1@3022.01,1120 3022.01,1195.49 3017.68,1199.82 C4.2@3017.68,1275
NetC8_1: C8.1 R11.1 R15.2 R16.2 | length 189.3
  Bottom Layer w20: C8.1@3768,255 R16.2@3768,202.5 v1(3805,202.5) ; R15.2@3825,254.5 3805,234.5 v1(3805,202.5) ; R11.1@3844.5,202.5 v1(3805,202.5)
NetC10_1: C10.1 D8.1 Q1.1 Q5.3 R4.2 | length 1186.5
  Top Layer w20: Q1.1@899.29,44.29 1083.58,-140 1472.5,-140 v1(1545,-67.5)
  Bottom Layer w20: R4.2@822.5,-2.91 869.7,44.29 Q1.1@899.29,44.29 ; Q5.3@1416.34,-102.5 1510,-102.5 v1(1545,-67.5) ; C10.1@1530,-13 1530,-25 1545,-40 v1(1545,-67.5) ; D8.1@1652.5,-131.97 1609.47,-131.97 v1(1545,-67.5)
NetC11_1: C11.1 J1.1 L3.1 RV2.2 | length 896.5
  Bottom Layer w70: RV2.2@-147.83,1009.86 -147.83,992.83 J1.1@25,820 -75,720 C11.1@-75,696.85 -75,617.5 42.5,500 267.5,500
NetC12_1: C12.1 F1.1 L4.2 | length 1023.2
  Bottom Layer w75: C12.1@190,928.15 525,593.15 525,426.2 L4.2@523.8,425 523.8,336.2 685,175 F1.1@749.02,175
NetC12_2: C12.2 L4.3 L5.2 | length 560.6
  Bottom Layer w75: C12.2@177.5,1328.7 177.5,1240 480.69,936.81 L4.3@523.8,936.81
NetC13_1: C13.1 D3.2 L4.1 | length 1463.2
  Bottom Layer w60: L4.1@917.5,425 987.5,355 D3.2@1260,355
  Bottom Layer w75: C13.1@454.72,1325 700,1079.72 700,642.5 L4.1@917.5,425
NetC13_2: C13.2 D3.3 L4.4 | length 1098.3
  Bottom Layer w60: 917.5,705 1117.5,505 D3.3@1260,505
  Bottom Layer w75: 917.5,705 L4.4@917.5,936.81 917.5,1197.22 C13.2@1045.28,1325
NetC14_2: C14.2 J3.1 L5.1 RV2.1 | length 1222.1
  Top Layer w75: RV2.1@-2.17,1305.14 -2.17,1237.17 95,1140 260,1140 355,1045 355,761 265.85,671.85 C14.2@150,671.85
  Bottom Layer w75: RV2.1@-2.17,1305.14 -2.17,1422.83 J3.1@50,1475
NetC15_1: C15.1 C45.1 D7.1 Q4.3 R10.2 | length 418.9
  Top Layer w20: C15.1@3997.09,-92.5 3997.09,-14.63 C45.1@4026.71,15
  Bottom Layer w20: R10.2@3935,92 3979.5,92 3980.34,91.16 Q4.3@4027.5,91.16 4027.5,55 4026.71,54.21 C45.1@4026.71,15 4026.71,-72.76 D7.1@3996.97,-102.5
NetC17_1: C17.1 C20.1 D9.1 D10.1 D17.2 R26.2 U2.4 U5.8 | length 3268
  Top Layer w20: v1(1550,735) 1550,521.97 1642.5,429.47 v1(1642.5,242.5) ; v1(1872.5,267.5) v1(1872.5,430) ; v1(2312.5,405) 2342.5,405 2425,322.5 v1(2467.5,322.5)
  Bottom Layer w20: C17.1@1267.5,45 1347.5,125 1416.97,125 D9.1@1462.5,79.47 1508.03,125 1632.5,125 ; R26.2@1537,532.5 C20.1@1537,582.5 1537,607 1537.5,607.5 1535,610 U5.8@1535,663.01 1535,720 v1(1550,735) ; D10.1@1745,-3.03 1720,21.97 1720,37.5 1632.5,125 ; v1(1872.5,267.5) 1805,267.5 1780,242.5 v1(1642.5,242.5) 1632.5,232.5 1632.5,125 ; v1(1872.5,430) 1872.5,491.59 D17.2@1924.41,543.5 1940,527.91 1940,507.5 1957.5,490 2250,490 2312.5,427.5 v1(2312.5,405) ; v1(2467.5,322.5) 2895,322.5 2972.5,400 U2.4@3032.83,400
NetC18_1: C18.1 R14.1 | length 111.7
  Bottom Layer w20: R14.1@3783,135 3832,135 C18.1@3845,148 3883,148 v1(3887.5,152.5)
NetC18_2: C18.2 C34.1 R15.1 U1.2 | length 449
  Bottom Layer w10: C34.1@3768,307.5 3750,307.5 3740,297.5 3740,180 3755,165 3755,95 3773.66,76.34 U1.2@3792.4,76.34 3792.4,62.6 3805,50 v1(3830,50) 3830,77 C18.2@3845,92
  Bottom Layer w20: C34.1@3768,307.5 3797.5,307.5 3800.5,310.5 R15.1@3825,310.5
NetC19_2: C19.2 R22.2 | length 90.2
  Bottom Layer w20: C19.2@4464.59,1137.5 4464.59,1184.59 4465,1185 R22.2@4465,1227.5
NetC21_1: C21.1 R23.1 U2.2 U3.3 | length 1894.8
  Top Layer w20: v1(3990,702.5) 3990,810 4092.5,912.5 4400,912.5 v1(4437.5,950)
  Bottom Layer w20: U2.2@3387.17,300 3411.67,324.5 R23.1@3460,324.5 3499.5,324.5 3512.5,337.5 3512.5,430 3582.5,500 3652.5,500 3695,542.5 3812.5,542.5 3875,605 3962.5,605 3990,632.5 v1(3990,702.5) ; v1(4437.5,950) 4457.5,970 4670,970 4697.24,997.24 U3.3@4697.24,1022.6 4752.6,1022.6 4787.91,1057.91 C21.1@4795,1057.91
NetC21_2: C21.2 R29.2 | length 84.7
  Bottom Layer w20: R29.2@4710.5,1172.5 4742.5,1172.5 4742.91,1172.09 C21.2@4795,1172.09
NetC22_1: C22.1 D13.1 R25.1 R26.1 | length 465.1
  Bottom Layer w10: R25.1@1482.5,632 1507.5,607 1507.5,510 1517.5,500 1560.5,500 R26.1@1593,532.5
  Bottom Layer w20: R26.1@1593,532.5 1607.5,518 1607.5,492.5 1596.97,481.97 D13.1@1596.97,440 1632.5,440 1633,439.5 C22.1@1667.5,439.5 1682,425 v1(1717.5,425)
NetC23_1: C23.1 R32.1 | length 189.9
  Bottom Layer w10: R32.1@1535,1068 1535,1047.5 1542.5,1040 1627.5,1040 1635,1047.5 C23.1@1635,1068
  Bottom Layer w20: C23.1@1635,1068 1677,1068 v1(1677.5,1067.5)
NetC23_2: C23.2 C36.1 R34.1 U5.2 | length 269.7
  Bottom Layer w20: U5.2@1585,851.99 1585,919.5 R34.1@1605.5,940 1605.5,964.5 1585,985 C36.1@1585,1012 1609.5,1012 C23.2@1635,1012 1635.5,1012.5 v1(1677.5,1012.5)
